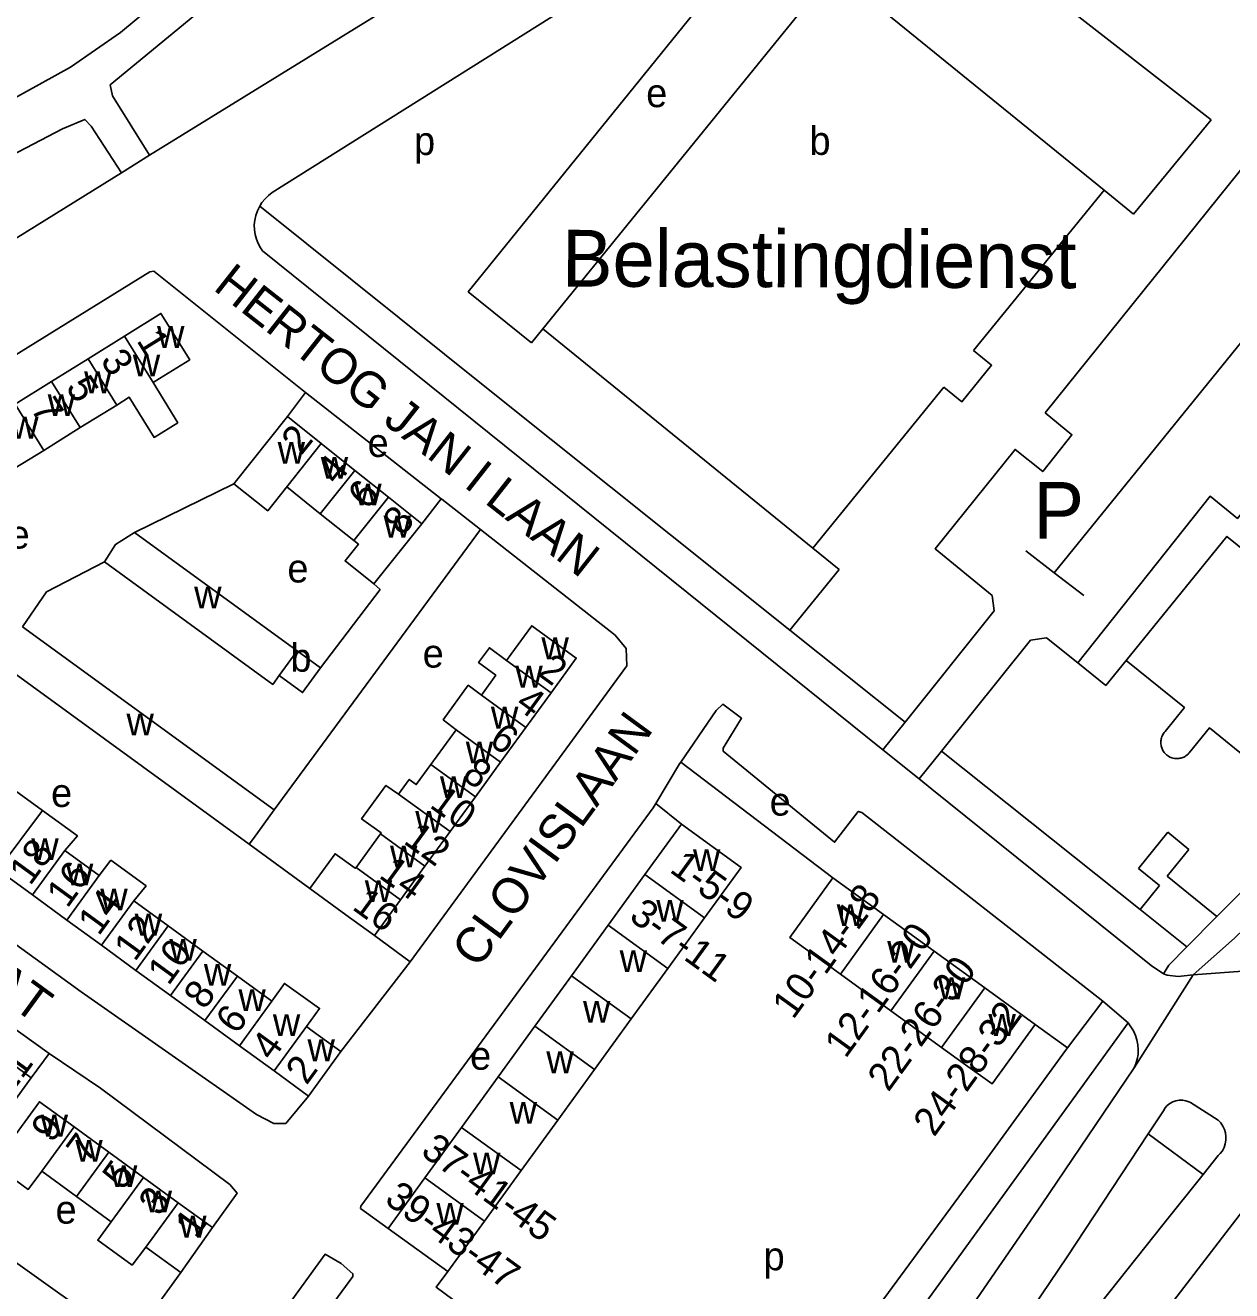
# Model space of a CAD drawing. Extents: x 159700 to 161346, y 381730 to 382922.
# Drawn here: x 160249.2 to 160419.2, y 382582.1 to 382760.5 of the extents above; entities that cross this region are included whole.
import ezdxf

# ---------------------------------------------------------------- set-up
doc = ezdxf.new("R2010")
doc.units = 0
for name, color, linetype in [('BLT_Basislijn', 7, 'Continuous'), ('BLT_Bebouwing', 7, 'Continuous'), ('BLT_Bebouwing_beschrifting', 7, 'Continuous'), ('BLT_Centroide', 7, 'Continuous'), ('BLT_Huisnummer', 7, 'Continuous'), ('BLT_Huisnummer_ tussenligend', 7, 'Continuous'), ('BLT_Huisnummer_reeks', 7, 'Continuous'), ('BLT_Onderverdeling_panden', 7, 'Continuous'), ('BLT_Straatnaam', 7, 'Continuous'), ('BLT_Tekst_parkeren', 7, 'Continuous'), ('BLT_Vlakafsluiter', 7, 'Continuous')]:
    doc.layers.add(name, color=color, linetype=linetype)

msp = doc.modelspace()

# ---------------------------------------------------------------- linework, layer by layer
at = {"layer": 'BLT_Basislijn'}
for p, q in [((160391.02, 382766.93), (160416.34, 382747.15)), ((160405.41, 382733.88), (160416.34, 382747.15)), ((160262.71, 382739.72), (160266.65, 382742.18)), ((160401.24, 382737.27), (160405.41, 382733.88)), ((160282.21, 382735.02), (160314.89, 382708.8)), ((160394.2, 382683.31), (160434.18, 382732.58)), ((160282.59, 382728.7), (160370.07, 382658.36)), ((160322.12, 382717.7), (160320.5, 382715.71)), ((160286.12, 382705.32), (160288.64, 382708.73)), ((160307.77, 382693.75), (160288.64, 382708.73)), ((160356.94, 382675.23), (160314.89, 382708.8)), ((160264.54, 382689.01), (160278.57, 382695.87)), ((160305.06, 382690.2), (160307.77, 382693.75)), ((160284.25, 382649.88), (160313.32, 382689.42)), ((160360.2, 382686.78), (160363.89, 382683.78)), ((160390.21, 382686.38), (160394.2, 382683.31)), ((160363.89, 382683.78), (160356.94, 382675.23)), ((160394.2, 382683.31), (160398.39, 382680.09)), ((160299.17, 382680.96), (160298.3, 382681.74)), ((160290.78, 382669.91), (160299.17, 382680.96)), ((160385.73, 382677.94), (160373.19, 382662.27)), ((160390.87, 382673.81), (160378.31, 382658.18)), ((160397.54, 382670.63), (160401.5, 382667.42)), ((160401.5, 382667.42), (160404.37, 382670.95)), ((160373.19, 382662.27), (160370.07, 382658.36)), ((160370.07, 382658.36), (160375.16, 382654.26)), ((160378.31, 382658.18), (160375.16, 382654.26)), ((160378.31, 382658.18), (160406.31, 382635.84)), ((160341.57, 382656.62), (160363.02, 382640.28)), ((160375.16, 382654.26), (160376.95, 382652.82)), ((160341.66, 382647.87), (160338.04, 382650.77)), ((160406.1, 382641.63), (160410.23, 382646.72)), ((160413.19, 382644.31), (160410.23, 382646.72)), ((160280.73, 382645.03), (160289.26, 382638.78)), ((160410.12, 382640.53), (160413.19, 382644.31)), ((160406.1, 382641.63), (160409.06, 382639.23)), ((160417.13, 382634.83), (160410.12, 382640.53)), ((160406.31, 382635.84), (160409.06, 382639.23)), ((160406.31, 382635.84), (160412.93, 382630.56)), ((160417.13, 382634.83), (160412.93, 382630.56)), ((160298.38, 382632.15), (160303.42, 382628.47)), ((160303.42, 382628.47), (160293.65, 382615.8)), ((160396.1, 382616.35), (160401.07, 382622.9)), ((160404.62, 382619.84), (160401.07, 382622.9)), ((160396.1, 382616.35), (160391.54, 382619.64)), ((160252.52, 382615.54), (160249.99, 382612.12)), ((160405.5, 382613.52), (160392.4, 382594.2)), ((160413.42, 382608.61), (160417.35, 382606.12)), ((160409.6, 382607.45), (160407.46, 382604.21)), ((160407.46, 382604.21), (160415.22, 382598.49)), ((160417.35, 382601.14), (160415.22, 382598.49)), ((160271.06, 382584.67), (160263.83, 382574.65))]:
    msp.add_line(p, q, dxfattribs=at)
for points in [[(160197.3, 382721.22), (160240.71, 382743.85), (160240.43, 382746.28), (160255.54, 382754.6), (160262.58, 382759.48), (160270.55, 382766.14), (160278.64, 382775.13), (160285, 382784.67), (160297.93, 382809.88), (160298.52, 382811.54), (160298.27, 382812.49), (160291.05, 382809.72), (160269.91, 382800.33), (160239.43, 382785.14), (160214.46, 382769.94), (160181.11, 382747.41)], [(160266.65, 382742.18), (160261.47, 382750.54), (160261.1, 382752.09), (160273.08, 382761.93), (160275.94, 382764.85), (160283.94, 382774.7), (160285.31, 382776.67), (160293.41, 382790.92), (160295.55, 382794.93)], [(160266.65, 382742.18), (160346.73, 382791.6)], [(160283.98, 382736.93), (160342.09, 382773.47), (160357.48, 382782.82)], [(160358.33, 382777.02), (160357.19, 382775.96), (160355.48, 382777.14), (160311.61, 382722.94), (160320.5, 382715.71)], [(160392.93, 382705.85), (160423.37, 382743.68), (160426.9, 382740.56), (160433.88, 382749.39)], [(160262.71, 382739.72), (160258.45, 382746.3), (160257.53, 382747.22), (160254.42, 382745.89), (160199.4, 382717.17)], [(160262.71, 382739.72), (160227.6, 382717.94), (160212.26, 382710.03), (160205.02, 382706.71)], [(160283.98, 382736.93), (160283.44, 382736.52), (160282.95, 382736.05), (160282.52, 382735.52), (160282.21, 382735.02)], [(160282.21, 382735.02), (160281.87, 382734.34), (160281.65, 382733.7), (160281.5, 382733.03), (160281.44, 382732.36), (160281.46, 382731.68), (160281.55, 382731.01), (160281.73, 382730.35), (160281.98, 382729.72), (160282.3, 382729.12), (160282.59, 382728.7)], [(160222.27, 382699.59), (160238.64, 382708.4), (160266.7, 382725.72), (160267.29, 382725.83), (160288.64, 382708.73)], [(160390.87, 382673.81), (160393.15, 382674.12), (160397.54, 382670.63), (160416.19, 382694.1), (160420.05, 382690.98), (160436.13, 382710.83), (160432.34, 382714)], [(160385.73, 382677.94), (160385.48, 382680.09), (160377.45, 382686.69), (160388.69, 382700.71), (160392.59, 382697.57), (160396.71, 382702.78), (160392.93, 382705.85)], [(160313.32, 382689.42), (160307.86, 382693.68), (160307.77, 382693.75)], [(160313.32, 382689.42), (160332.3, 382674.53), (160333.89, 382672.62), (160333.98, 382670.18), (160303.42, 382628.47)], [(160248.77, 382675.71), (160252.16, 382680.61), (160260.34, 382684.83)], [(160467.05, 382683.96), (160419.05, 382636.78), (160417.13, 382634.83)], [(160356.94, 382675.23), (160373.19, 382662.27)], [(160341.57, 382656.62), (160346.54, 382663.91), (160347.5, 382664.77), (160350.14, 382662.8), (160347.56, 382658.57), (160347.56, 382658.15), (160363.24, 382645.31), (160366.58, 382649.66), (160367.11, 382649.52), (160401.07, 382622.9)], [(160193.83, 382658.06), (160232.83, 382629.65), (160252.52, 382615.54)], [(160341.57, 382656.62), (160341.4, 382656.36), (160338.04, 382650.77)], [(160446.43, 382657.59), (160419.61, 382631.81), (160413.81, 382626.64)], [(160409.6, 382626.78), (160407.89, 382627.96), (160376.95, 382652.82)], [(160221.63, 382649.82), (160257.03, 382624.25), (160281.76, 382606.94), (160284.18, 382605.68), (160285.88, 382605.65), (160289.09, 382609.54)], [(160300.33, 382590.86), (160296.39, 382593.69), (160296.45, 382594.01), (160337.68, 382650.18), (160338.04, 382650.77)], [(160412.93, 382630.56), (160410.39, 382627.98), (160409.6, 382626.78)], [(160413.81, 382626.64), (160411.68, 382626.37), (160410.16, 382626.59), (160409.6, 382626.78)], [(160252.43, 382410.59), (160268.55, 382433.33), (160270.86, 382436.59), (160273.99, 382440.53), (160346.07, 382539.47), (160347.92, 382545.02), (160359.65, 382560.71), (160368.2, 382569.53), (160404.62, 382619.84)], [(160404.62, 382619.84), (160405.04, 382619.3), (160405.39, 382618.71), (160405.67, 382618.09), (160405.88, 382617.44), (160406.01, 382616.77), (160406.06, 382616.09), (160406.03, 382615.41), (160405.92, 382614.73), (160405.73, 382614.08), (160405.5, 382613.52)], [(160252.52, 382615.54), (160259.77, 382610.64), (160277.98, 382597.07), (160279.01, 382595.84), (160275.53, 382590.98)], [(160346.98, 382549.35), (160383.64, 382599.24), (160395.79, 382615.95), (160396.1, 382616.35)], [(160409.6, 382607.45), (160409.85, 382607.85), (160410.16, 382608.2), (160410.52, 382608.5), (160410.93, 382608.72), (160411.37, 382608.88), (160411.84, 382608.96), (160412.31, 382608.96), (160412.77, 382608.87), (160413.21, 382608.72), (160413.42, 382608.61)], [(160417.35, 382606.12), (160417.7, 382605.74), (160417.99, 382605.3), (160418.21, 382604.83), (160418.36, 382604.33), (160418.43, 382603.82), (160418.42, 382603.3), (160418.33, 382602.79), (160418.16, 382602.29), (160417.92, 382601.83), (160417.61, 382601.41), (160417.35, 382601.14)], [(160407.46, 382604.21), (160396.02, 382586.87), (160388.69, 382576), (160377.57, 382560.55), (160374.82, 382556.76)], [(160425.28, 382599.18), (160384.45, 382546.02), (160383.14, 382544.19), (160379.74, 382536.86), (160366.91, 382518.26), (160360.11, 382511.98), (160356.18, 382508.31), (160321.11, 382459.87)], [(160415.22, 382598.49), (160409.51, 382591.38), (160395.76, 382574.04), (160381.75, 382556.63)], [(160236.76, 382593.95), (160237.89, 382593.13), (160263.83, 382574.65)], [(160370.94, 382564.35), (160375.13, 382569.06), (160392.4, 382594.2)], [(160286.74, 382580.76), (160291.43, 382587.22), (160293.69, 382585.93), (160295.34, 382584.47), (160295.34, 382584.08), (160290.68, 382577.74)], [(160342.56, 382552.33), (160343.84, 382554.73), (160342.93, 382555.66), (160341.77, 382557.82), (160341.96, 382560.58), (160345.59, 382565.7), (160345.43, 382566.81), (160344.95, 382567.45), (160342.35, 382568.82), (160339.71, 382565.13), (160338.12, 382563.86), (160336.21, 382563.24), (160332.93, 382563.48), (160307.08, 382582.59), (160308.72, 382584.78)]]:
    msp.add_lwpolyline(points, dxfattribs=at)
at = {"layer": 'BLT_Bebouwing'}
for p, q in [((160401.24, 382737.27), (160382.85, 382714.63)), ((160263.14, 382716.68), (160258, 382713.48)), ((160258, 382713.48), (160252.85, 382710.29)), ((160252.85, 382710.29), (160247.71, 382707.09)), ((160262.05, 382706.96), (160256.9, 382703.77)), ((160286.12, 382705.32), (160278.57, 382695.87)), ((160290.89, 382701.52), (160286.12, 382705.32)), ((160256.9, 382703.77), (160251.76, 382700.57)), ((160295.61, 382697.74), (160290.89, 382701.52)), ((160251.76, 382700.57), (160246.62, 382697.38)), ((160300.34, 382693.97), (160295.61, 382697.74)), ((160286.01, 382695.41), (160290.73, 382691.64)), ((160305.06, 382690.2), (160300.34, 382693.97)), ((160290.73, 382691.64), (160295.46, 382687.86)), ((160300.18, 382684.09), (160305.06, 382690.2)), ((160287.49, 382672.3), (160264.54, 382689.01)), ((160284.25, 382649.88), (160248.77, 382675.71)), ((160280.73, 382645.03), (160245.25, 382670.86)), ((160290.78, 382669.91), (160287.49, 382672.3)), ((160319.72, 382661.5), (160323.28, 382666.39)), ((160309.89, 382661.17), (160306.33, 382656.28)), ((160316.17, 382656.61), (160319.72, 382661.5)), ((160409.85, 382660.93), (160409.78, 382660.84)), ((160312.61, 382651.72), (160316.17, 382656.61)), ((160413.25, 382657.92), (160413.17, 382657.83)), ((160309.05, 382646.82), (160312.61, 382651.72)), ((160341.66, 382647.87), (160336.5, 382640.75)), ((160299.21, 382646.5), (160295.78, 382641.78)), ((160305.5, 382641.93), (160309.05, 382646.82)), ((160259.58, 382640.61), (160254.72, 382644.15)), ((160250.15, 382637.88), (160245.29, 382641.43)), ((160302.06, 382637.21), (160305.5, 382641.93)), ((160336.5, 382640.75), (160331.33, 382633.62)), ((160370.15, 382635.12), (160363.02, 382640.28)), ((160255.02, 382634.34), (160250.15, 382637.88)), ((160269.32, 382633.52), (160264.45, 382637.06)), ((160298.38, 382632.15), (160302.06, 382637.21)), ((160377.28, 382629.96), (160370.15, 382635.12)), ((160259.89, 382630.8), (160255.02, 382634.34)), ((160274.18, 382629.98), (160269.32, 382633.52)), ((160331.33, 382633.62), (160326.16, 382626.49)), ((160339.73, 382627.53), (160344.89, 382634.66)), ((160264.75, 382627.25), (160259.89, 382630.8)), ((160279.05, 382626.43), (160274.18, 382629.98)), ((160384.41, 382624.8), (160377.28, 382629.96)), ((160269.62, 382623.71), (160264.75, 382627.25)), ((160283.92, 382622.89), (160279.05, 382626.43)), ((160326.16, 382626.49), (160321, 382619.37)), ((160334.56, 382620.41), (160339.73, 382627.53)), ((160371.2, 382621.56), (160364.07, 382626.72)), ((160391.54, 382619.64), (160384.41, 382624.8)), ((160274.49, 382620.17), (160269.62, 382623.71)), ((160378.33, 382616.4), (160371.2, 382621.56)), ((160279.35, 382616.62), (160274.49, 382620.17)), ((160321, 382619.37), (160315.83, 382612.24)), ((160329.39, 382613.28), (160334.56, 382620.41)), ((160245.1, 382615.68), (160249.99, 382612.12)), ((160284.22, 382613.08), (160279.35, 382616.62)), ((160293.65, 382615.8), (160289.09, 382609.54)), ((160249.99, 382612.12), (160245.38, 382605.79)), ((160289.09, 382609.54), (160284.22, 382613.08)), ((160315.83, 382612.24), (160310.66, 382605.12)), ((160324.23, 382606.15), (160329.39, 382613.28)), ((160256.03, 382605.17), (160260.93, 382601.61)), ((160310.66, 382605.12), (160305.49, 382597.99)), ((160319.06, 382599.03), (160324.23, 382606.15)), ((160260.93, 382601.61), (160265.82, 382598.05)), ((160256.38, 382595.36), (160251.48, 382598.92)), ((160265.82, 382598.05), (160270.71, 382594.48)), ((160305.49, 382597.99), (160300.33, 382590.86)), ((160313.89, 382591.9), (160319.06, 382599.03)), ((160261.27, 382591.8), (160256.38, 382595.36)), ((160270.71, 382594.48), (160275.53, 382590.98)), ((160275.53, 382590.98), (160271.06, 382584.67)), ((160300.33, 382590.86), (160308.72, 382584.78)), ((160308.72, 382584.78), (160313.89, 382591.9)), ((160271.06, 382584.67), (160266.16, 382588.23))]:
    msp.add_line(p, q, dxfattribs=at)
for points in [[(160363.14, 382768.21), (160322.12, 382717.7)], [(160363.14, 382768.21), (160401.24, 382737.27)], [(160404.37, 382670.95), (160418.56, 382688.43), (160423.15, 382684.7), (160425.96, 382688.15), (160424.12, 382689.64), (160438.38, 382707.2), (160440.17, 382705.75), (160442.95, 382709.18), (160438.31, 382712.94), (160452.52, 382730.44)], [(160267.19, 382710.16), (160268.08, 382710.71), (160272.33, 382713.35), (160268.28, 382719.87), (160263.14, 382716.68)], [(160322.12, 382717.7), (160360.2, 382686.78)], [(160378.65, 382709.5), (160381.2, 382707.43), (160385.38, 382712.58), (160382.85, 382714.63)], [(160267.19, 382710.16), (160270.64, 382704.47), (160267.32, 382702.4), (160263.8, 382708.05), (160262.05, 382706.96)], [(160360.2, 382686.78), (160378.65, 382709.5)], [(160278.57, 382695.87), (160283.34, 382692.06), (160286.01, 382695.41)], [(160264.54, 382689.01), (160261.86, 382687.3), (160260.34, 382684.83)], [(160295.46, 382687.86), (160296.12, 382687.34), (160294.24, 382684.98), (160298.3, 382681.74)], [(160260.34, 382684.83), (160284.05, 382667.56), (160284.95, 382668.81)], [(160298.3, 382681.74), (160300.18, 382684.09)], [(160323.28, 382666.39), (160326.83, 382671.28), (160320.55, 382675.84), (160317.61, 382671.8), (160317, 382670.96)], [(160317, 382670.96), (160314.59, 382672.75), (160313.05, 382670.64), (160315.48, 382668.87), (160313.45, 382666.06)], [(160409.85, 382660.93), (160412.56, 382664.3), (160404.37, 382670.95)], [(160284.95, 382668.81), (160288.24, 382666.42), (160290.78, 382669.91)], [(160313.45, 382666.06), (160311.6, 382667.45), (160308.07, 382662.59), (160309.89, 382661.17)], [(160409.78, 382660.84), (160409.72, 382660.77), (160409.62, 382660.65), (160409.55, 382660.52), (160409.47, 382660.38), (160409.4, 382660.21), (160409.34, 382660.05), (160409.3, 382659.91), (160409.27, 382659.75), (160409.25, 382659.6), (160409.24, 382659.49), (160409.24, 382659.32), (160409.25, 382659.17), (160409.27, 382659.02), (160409.29, 382658.89), (160409.32, 382658.76), (160409.37, 382658.64), (160409.42, 382658.51), (160409.47, 382658.38), (160409.54, 382658.25), (160409.61, 382658.13), (160409.72, 382657.98), (160409.81, 382657.88), (160409.93, 382657.75), (160410.05, 382657.64), (160410.18, 382657.53), (160410.35, 382657.43), (160410.52, 382657.33), (160410.67, 382657.26), (160410.81, 382657.22), (160410.98, 382657.17), (160411.18, 382657.13), (160411.34, 382657.11), (160411.49, 382657.11), (160411.63, 382657.11), (160411.79, 382657.12), (160411.94, 382657.15), (160412.07, 382657.17), (160412.21, 382657.21), (160412.34, 382657.26), (160412.49, 382657.33), (160412.66, 382657.42), (160412.78, 382657.49), (160412.97, 382657.64), (160413.08, 382657.74), (160413.17, 382657.83)], [(160421.88, 382656.73), (160416.09, 382661.44), (160413.25, 382657.92)], [(160306.33, 382656.28), (160304.27, 382653.45), (160303.29, 382654.17), (160301.79, 382652.1)], [(160251.56, 382649.8), (160246.74, 382653.32), (160244.98, 382651.24)], [(160301.79, 382652.1), (160299.99, 382653.34), (160296.57, 382648.64), (160299.32, 382646.65), (160299.21, 382646.5)], [(160254.72, 382644.15), (160256.51, 382646.2), (160251.56, 382649.8)], [(160284.25, 382649.88), (160281.31, 382645.83), (160280.73, 382645.03)], [(160344.89, 382634.66), (160350.06, 382641.78), (160341.66, 382647.87)], [(160264.45, 382637.06), (160266.19, 382639.16), (160261.22, 382642.77), (160259.58, 382640.61)], [(160295.78, 382641.78), (160295.68, 382641.64), (160292.84, 382643.7), (160289.26, 382638.78)], [(160363.02, 382640.28), (160360.09, 382636.24), (160356.94, 382631.89), (160364.07, 382626.72)], [(160289.26, 382638.78), (160294.34, 382635.09), (160298.38, 382632.15)], [(160288.78, 382619.35), (160290.64, 382621.9), (160285.69, 382625.41), (160283.92, 382622.89)], [(160288.78, 382619.35), (160289.61, 382618.74), (160293.65, 382615.8)], [(160391.54, 382619.64), (160385.45, 382611.24), (160381.4, 382614.17), (160378.33, 382616.4)], [(160251.48, 382598.92), (160249.57, 382596.36), (160244.71, 382599.9), (160246.59, 382602.49), (160251.14, 382608.74), (160256.03, 382605.17)], [(160266.16, 382588.23), (160264.22, 382585.69), (160259.38, 382589.21), (160261.27, 382591.8)]]:
    msp.add_lwpolyline(points, dxfattribs=at)
at = {"layer": 'BLT_Onderverdeling_panden'}
for p, q in [((160267.19, 382710.16), (160263.14, 382716.68)), ((160262.05, 382706.96), (160258, 382713.48)), ((160256.9, 382703.77), (160252.85, 382710.29)), ((160251.76, 382700.57), (160247.71, 382707.09)), ((160290.89, 382701.52), (160286.01, 382695.41)), ((160295.61, 382697.74), (160290.73, 382691.64)), ((160300.34, 382693.97), (160295.46, 382687.86)), ((160287.49, 382672.3), (160284.95, 382668.81)), ((160323.28, 382666.39), (160317, 382670.96)), ((160319.72, 382661.5), (160313.45, 382666.06)), ((160316.17, 382656.61), (160309.89, 382661.17)), ((160312.61, 382651.72), (160306.33, 382656.28)), ((160309.05, 382646.82), (160301.79, 382652.1)), ((160251.56, 382649.8), (160245.29, 382641.43)), ((160305.5, 382641.93), (160299.21, 382646.5)), ((160254.72, 382644.15), (160250.15, 382637.88)), ((160259.58, 382640.61), (160255.02, 382634.34)), ((160302.06, 382637.21), (160295.78, 382641.78)), ((160344.89, 382634.66), (160336.5, 382640.75)), ((160264.45, 382637.06), (160259.89, 382630.8)), ((160364.07, 382626.72), (160370.15, 382635.12)), ((160269.32, 382633.52), (160264.75, 382627.25)), ((160339.73, 382627.53), (160331.33, 382633.62)), ((160274.18, 382629.98), (160269.62, 382623.71)), ((160371.2, 382621.56), (160377.28, 382629.96)), ((160279.05, 382626.43), (160274.49, 382620.17)), ((160334.56, 382620.41), (160326.16, 382626.49)), ((160378.33, 382616.4), (160384.41, 382624.8)), ((160283.92, 382622.89), (160279.35, 382616.62)), ((160288.78, 382619.35), (160284.22, 382613.08)), ((160329.39, 382613.28), (160321, 382619.37)), ((160324.23, 382606.15), (160315.83, 382612.24)), ((160251.48, 382598.92), (160256.03, 382605.17)), ((160319.06, 382599.03), (160310.66, 382605.12)), ((160256.38, 382595.36), (160260.93, 382601.61)), ((160261.27, 382591.8), (160265.82, 382598.05)), ((160313.89, 382591.9), (160305.49, 382597.99)), ((160266.16, 382588.23), (160270.71, 382594.48))]:
    msp.add_line(p, q, dxfattribs=at)
at = {"layer": 'BLT_Vlakafsluiter'}
for q in [(160405.5, 382613.52), (160425.54, 382627.48)]:
    msp.add_line((160413.81, 382626.64), q, dxfattribs=at)

# ---------------------------------------------------------------- texts
at = {"layer": 'BLT_Bebouwing_beschrifting'}
msp.add_text('Belastingdienst', height=8, rotation=359.803, dxfattribs=at).set_placement((160324.8, 382723.67))
at = {"layer": 'BLT_Centroide'}
for s, p in [('e', (160336.69, 382748.96)), ('b', (160359.71, 382742.23)), ('p', (160303.96, 382742.21)), ('w', (160267.73, 382715.02)), ('w', (160264.31, 382711)), ('w', (160257.45, 382708.62)), ('w', (160252.31, 382705.42)), ('w', (160247.16, 382702.23)), ('e', (160297.41, 382699.64)), ('w', (160284.73, 382698.69)), ('w', (160290.81, 382696.58)), ('w', (160295.53, 382692.81)), ('w', (160299.66, 382688.28)), ('e', (160246.8, 382686.72)), ('e', (160286.11, 382681.94)), ('w', (160272.96, 382678.28)), ('w', (160321.92, 382671.12)), ('b', (160286.53, 382669.36)), ('e', (160305.18, 382669.94)), ('w', (160318.24, 382667.12)), ('w', (160263.42, 382660.38)), ('w', (160314.8, 382661.34)), ('w', (160311.25, 382656.44)), ('w', (160307.61, 382651.56)), ('e', (160252.79, 382650.29)), ('e', (160354.1, 382649.07)), ('w', (160304.13, 382646.66)), ('w', (160250, 382642.8)), ('w', (160300.57, 382641.78)), ('w', (160343.28, 382641.25)), ('w', (160254.88, 382639.23)), ('w', (160259.73, 382635.7)), ('w', (160297.02, 382636.88)), ('w', (160338.11, 382634.12)), ('w', (160264.59, 382632.16)), ('w', (160363.55, 382633.5)), ('w', (160269.47, 382628.61)), ('w', (160370.67, 382628.34)), ('w', (160332.95, 382627)), ('w', (160274.33, 382625.08)), ('w', (160377.8, 382623.19)), ('w', (160279.2, 382621.52)), ('w', (160327.78, 382619.88)), ('w', (160284.06, 382617.98)), ('w', (160384.94, 382618.02)), ('w', (160288.94, 382614.45)), ('e', (160311.86, 382613.24)), ('w', (160322.61, 382612.75)), ('w', (160317.44, 382605.62)), ('w', (160251.31, 382603.83)), ('w', (160256.2, 382600.27)), ('w', (160312.28, 382598.5)), ('w', (160261.09, 382596.69)), ('w', (160265.98, 382593.12)), ('e', (160253.42, 382591.54)), ('w', (160307.11, 382591.38)), ('w', (160270.84, 382589.59)), ('p', (160353.24, 382584.97))]:
    msp.add_text(s, height=4, dxfattribs=at).set_placement(p)
at = {"layer": 'BLT_Huisnummer'}
for s, rotation, p in [('1', 301.8471, (160264.76, 382716.06)), ('5', 301.8471, (160254.77, 382709.5)), ('2', 51.3883, (160288.06, 382699.76)), ('8', 51.3883, (160302.38, 382688.36)), ('2', 323.9819, (160321.21, 382668.98)), ('6', 323.9819, (160314.35, 382659.24)), ('10', 323.978, (160306, 382650.34)), ('18', 53.9417, (160249.84, 382639.07)), ('14', 323.984, (160298.84, 382640.42)), ('14', 53.9417, (160259.51, 382631.99)), ('16', 323.9895, (160295.08, 382635.96)), ('10', 53.9373, (160269.34, 382624.97)), ('6', 53.9373, (160278.95, 382618.07)), ('2', 53.9373, (160288.81, 382610.96)), ('9', 53.935, (160252.91, 382602.79)), ('5', 53.941, (160262.96, 382596.12)), ('1', 53.9454, (160273.17, 382589.31))]:
    msp.add_text(s, height=4, rotation=rotation, dxfattribs=at).set_placement(p)
at = {"layer": 'BLT_Huisnummer_ tussenligend'}
for s, rotation, p in [('3', 301.8471, (160259.67, 382713.28)), ('7', 301.8471, (160249.81, 382706.45)), ('4', 51.3883, (160293.11, 382695.53)), ('6', 51.3883, (160297.43, 382692.04)), ('4', 323.9819, (160318.06, 382664.4)), ('8', 323.9819, (160310.56, 382654.38)), ('12', 323.978, (160302.32, 382645.26)), ('16', 53.9417, (160255.08, 382635.9)), ('12', 53.9373, (160264.6, 382628.36)), ('8', 53.9373, (160274.42, 382621.56)), ('4', 53.9373, (160283.95, 382614.33)), ('11', 53.935, (160246.93, 382609.41)), ('7', 53.941, (160257.89, 382599.91)), ('3', 53.9454, (160268.06, 382592.43))]:
    msp.add_text(s, height=4, rotation=rotation, dxfattribs=at).set_placement(p)
at = {"layer": 'BLT_Huisnummer_reeks'}
for s, rotation, p in [('1-5-9', 324.0539, (160339.83, 382641.23)), ('10-14-18', 54.0872, (160357.41, 382620.2)), ('3-7-11', 324.0539, (160334.11, 382634.48)), ('12-16-20', 54.084, (160364.8, 382614.71)), ('22-26-30', 54.084, (160370.84, 382609.99)), ('24-28-32', 54.084, (160377.29, 382603.65)), ('37-41-45', 324.0539, (160304.74, 382601.35)), ('39-43-47', 324.0539, (160299.63, 382594.59))]:
    msp.add_text(s, height=4, rotation=rotation, dxfattribs=at).set_placement(p)
at = {"layer": 'BLT_Straatnaam'}
for s, rotation, p in [('HERTOG JAN I LAAN', 321.834, (160275.49, 382723.31)), ('CLOVISLAAN', 53.7239, (160312.99, 382627.36)), ('PEPIJNSTRAAT', 323.9202, (160210.25, 382648.96))]:
    msp.add_text(s, height=5, rotation=rotation, dxfattribs=at).set_placement(p)
at = {"layer": 'BLT_Tekst_parkeren'}
msp.add_text('P', height=8, dxfattribs=at).set_placement((160391.28, 382688.1))

doc.saveas('drawing.dxf')
